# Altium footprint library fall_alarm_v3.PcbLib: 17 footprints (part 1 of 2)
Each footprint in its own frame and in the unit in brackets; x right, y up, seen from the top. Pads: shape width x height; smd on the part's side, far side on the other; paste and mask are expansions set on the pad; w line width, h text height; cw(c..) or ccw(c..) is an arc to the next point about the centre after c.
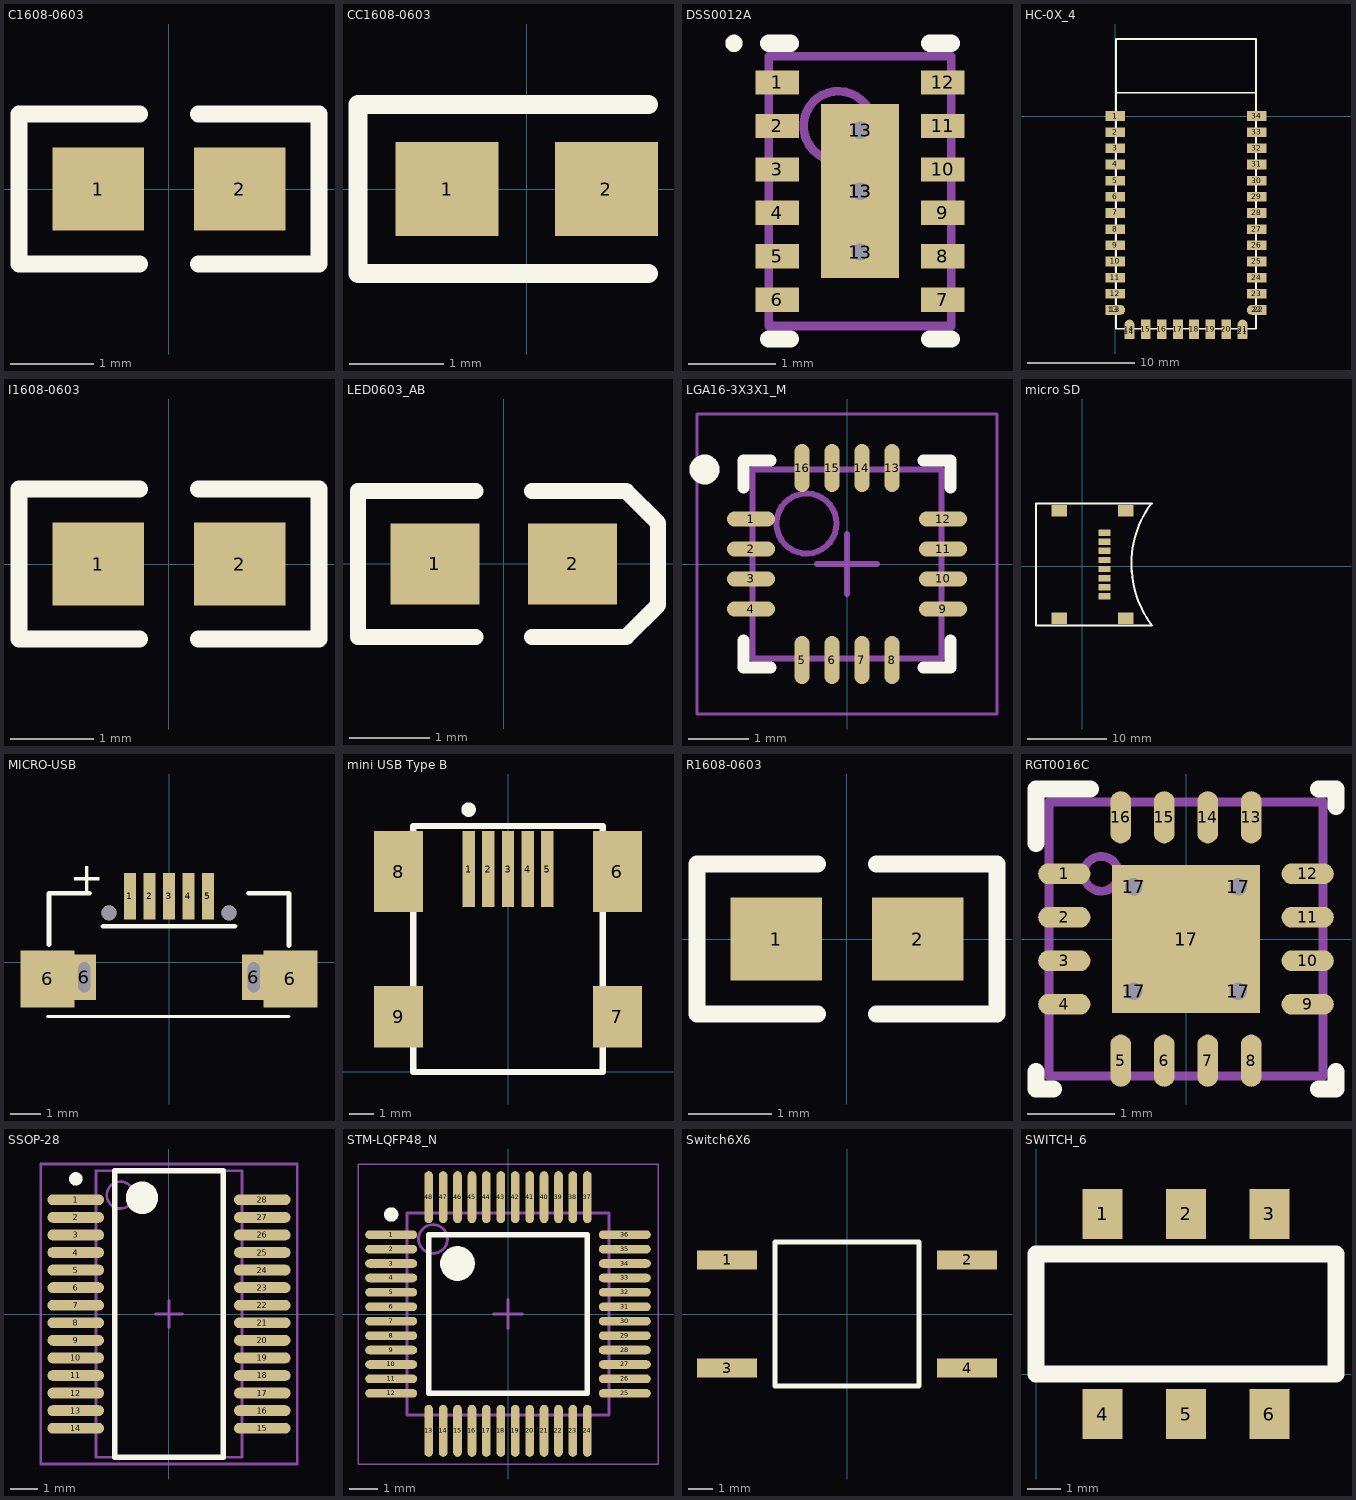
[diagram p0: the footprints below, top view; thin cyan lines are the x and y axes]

## C1608-0603 [mm]
pads (2):
  rect 1.1x1 smd: 1(-0.85,0) 2(0.85,0)
Top Overlay:
  lines w0.2: -0.35,-0.9 -1.8,-0.9 -1.8,0.9 -0.35,0.9 ; 0.35,-0.9 1.8,-0.9 1.8,0.9 0.35,0.9

## CC1608-0603 [mm]
pads (2):
  rect 1.1x1 smd: 1(-0.85,0) 2(0.85,0)
Top Overlay:
  lines w0.2: 1.3,-0.9 -1.8,-0.9 -1.8,0.9 1.3,0.9

## DSS0012A [mm]
pads (16):
  rect 0.5x0.28 smd paste-0.14 mask+0.076: 1(47.31,52.05) 2(47.31,51.55) 3(47.31,51.05) 4(47.31,50.55) 5(47.31,50.05) 6(47.31,49.55) 7(49.21,49.55) 8(49.21,50.05) 9(49.21,50.55) 10(49.21,51.05) 11(49.21,51.55) 12(49.21,52.05)
  round 0.5 / inner round 1.524 / far side round 0.5 hole 0.2 mask+0.051: 13(48.26,50.8) 13(48.26,50.1) 13(48.26,51.5)
  rect 0.9x2 smd paste-0.45 mask+0.076: 13(48.26,50.8)
Top Overlay:
  circle w0.1: c46.81,52.5 r0.05
  lines w0.2: 47.21,49.1 47.46,49.1 ; 47.21,52.5 47.46,52.5 ; 49.06,49.1 49.31,49.1 ; 49.06,52.5 49.31,52.5
Top Paste:
  region: 47.06,51.175 47.06,50.925 47.56,50.925 47.56,51.175
  region: 47.885,52.5 47.885,51.9 48.135,51.9 48.135,52.5
  region: 47.91,51.6 47.91,50 48.61,50 48.61,51.6
  region: 48.635,51.9 48.635,52.5 48.385,52.5 48.385,51.9
  region: 48.635,49.1 48.635,49.7 48.385,49.7 48.385,49.1
  region: 47.885,49.7 47.885,49.1 48.135,49.1 48.135,49.7
  region: 47.06,51.675 47.06,51.425 47.56,51.425 47.56,51.675
  region: 47.06,52.175 47.06,51.925 47.56,51.925 47.56,52.175
  region: 47.06,50.675 47.06,50.425 47.56,50.425 47.56,50.675
  region: 47.06,50.175 47.06,49.925 47.56,49.925 47.56,50.175
  region: 47.06,49.675 47.06,49.425 47.56,49.425 47.56,49.675
  region: 48.96,49.675 48.96,49.425 49.46,49.425 49.46,49.675
  region: 48.96,50.175 48.96,49.925 49.46,49.925 49.46,50.175
  region: 48.96,50.675 48.96,50.425 49.46,50.425 49.46,50.675
  region: 48.96,51.175 48.96,50.925 49.46,50.925 49.46,51.175
  region: 48.96,51.675 48.96,51.425 49.46,51.425 49.46,51.675
  region: 48.96,52.175 48.96,51.925 49.46,51.925 49.46,52.175
Mechanical 1:
  circle w0.1: c48.01,51.55 r0.4
  lines w0.1: 47.21,49.25 47.21,52.35 49.31,52.35 49.31,49.25 47.21,49.25

## HC-0X_4 [mm]
pads (38):
  rect 1.8x0.9 smd: 1(0,0) 2(0,-1.5) 3(0,-3) 4(0,-4.5) 5(0,-6) 6(0,-7.5) 7(0,-9) 8(0,-10.5) 9(0,-12) 10(0,-13.5) 11(0,-15) 12(0,-16.5) 23(13.1,-16.5) 24(13.1,-15) 25(13.1,-13.5) 26(13.1,-12) 27(13.1,-10.5) 28(13.1,-9) 29(13.1,-7.5) 30(13.1,-6) 31(13.1,-4.5) 32(13.1,-3) 33(13.1,-1.5) 34(13.1,0)
  rect 1.35x0.9 smd: 13(-0.225,-18) 22(13.325,-18)
  oval 1.8x0.9 smd: 13(0,-18) 22(13.1,-18)
  rect 0.9x1.35 smd: 14(1.3,-20.025) 21(11.8,-20.025)
  oval 0.9x1.8 smd: 14(1.3,-19.8) 21(11.8,-19.8)
  rect 0.9x1.8 smd: 15(2.8,-19.8) 16(4.3,-19.8) 17(5.8,-19.8) 18(7.3,-19.8) 19(8.8,-19.8) 20(10.3,-19.8)
Top Overlay:
  lines w0.152: 0.05,2.15 13.05,2.15 ; 0.05,-19.75 0.05,7.15 13.05,7.15 13.05,-19.75 0.05,-19.75

## I1608-0603 [mm]
pads (2):
  rect 1.1x1 smd: 1(-0.85,0) 2(0.85,0)
Top Overlay:
  lines w0.2: -0.35,-0.9 -1.8,-0.9 -1.8,0.9 -0.35,0.9 ; 0.35,-0.9 1.8,-0.9 1.8,0.9 0.35,0.9

## LED0603_AB [mm]
pads (2):
  rect 1.1x1 smd: 1(-0.85,0) 2(0.85,0)
Top Overlay:
  lines w0.2: -0.35,-0.9 -1.8,-0.9 -1.8,0.9 -0.35,0.9 ; 0.35,-0.9 1.513,-0.9 1.905,-0.508 1.905,0.508 1.513,0.9 0.35,0.9

## LGA16-3X3X1_M [mm] "PQFN, 16-Leads, Body 3x3mm, Pitch 0.5mm, IPC Low Density"
height 1
pads (16):
  oval 0.8x0.25 smd: 1(-1.6,0.75) 2(-1.6,0.25) 3(-1.6,-0.25) 4(-1.6,-0.75) 9(1.6,-0.75) 10(1.6,-0.25) 11(1.6,0.25) 12(1.6,0.75)
  oval 0.25x0.8 smd: 5(-0.75,-1.6) 6(-0.25,-1.6) 7(0.25,-1.6) 8(0.75,-1.6) 13(0.75,1.6) 14(0.25,1.6) 15(-0.25,1.6) 16(-0.75,1.6)
Top Overlay:
  circle w0.25: c-2.375,1.575 r0.125
  lines w0.2: -1.725,-1.275 -1.725,-1.725 -1.275,-1.725 ; -1.725,1.275 -1.725,1.725 -1.275,1.725 ; 1.275,-1.725 1.725,-1.725 1.725,-1.275 ; 1.275,1.725 1.725,1.725 1.725,1.275
Mechanical 13:
  circle w0.1: c-0.675,0.675 r0.5
  lines w0.1: -1.575,-1.575 1.575,-1.575 1.575,1.575 -1.575,1.575 -1.575,-1.575
Mechanical 15:
  lines w0.05: -2.5,-2.5 2.5,-2.5 2.5,2.5 -2.5,2.5 -2.5,-2.5
  lines w0.1: -0.5,0 0.5,0 ; 0,-0.5 0,0.5
3D body: height 1, standoff 0, extent -1.575,-1.575 1.575,1.575

## micro SD [mm]
pads (12):
  rect 1.5x0.8 smd: 1(2.794,4.191) 2(2.794,3.048) 3(2.794,1.905) 4(2.794,0.762) 5(2.794,-0.381) 6(2.794,-1.524) 7(2.794,-2.667) 8(2.794,-3.81)
  rect 2x1.45 smd: ""(-2.921,-6.604) ""(-2.921,6.985) ""(5.461,-6.604) ""(5.461,6.985)
Top Overlay:
  lines w0.254: 8.614,7.798 ccw(c19.05,0.254) 8.763,-7.493 -5.842,-7.493 -5.842,7.874 8.763,7.874

## MICRO-USB [mm]
pads (11):
  rect 0.4x1.55 smd: 1(-1.3,2.2) 2(-0.65,2.2) 3(0,2.2) 4(0.65,2.2) 5(1.3,2.2)
  rect 1.8x1.9 smd: 6(-4.05,-0.55) 6(4.05,-0.55)
  rect 0.8x1.5 hole 0.4 slot 1 at 90 deg: 6(-2.825,-0.5) 6(2.825,-0.5)
  round 0.5 hole 0.5 unplated: ""(-2,1.65) ""(2,1.65)
Top Overlay:
  lines w0.1: -4.05,-1.8 4,-1.8
  lines w0.152: -4,0.584 -4,2.3 -2.65,2.3 ; -2.2,1.2 2.2,1.2 ; 2.65,2.3 4,2.3 4,0.55
  text "+" at -3.3,2.35 h1

## mini USB Type B [mm]
pads (9):
  rect 0.5x3.1 smd: 1(-1.6,8.25) 2(-0.8,8.25) 3(0,8.25) 4(0.8,8.25) 5(1.6,8.25)
  rect 2x3.3 smd: 6(4.45,8.15) 8(-4.45,8.15)
  rect 2x2.5 smd: 7(4.45,2.25) 9(-4.45,2.25)
Top Overlay:
  circle w0.3: c-1.6,10.668 r0.146
  lines w0.254: -3.85,0 3.85,0 3.85,10 -3.85,10 -3.85,0

## R1608-0603 [mm]
pads (2):
  rect 1.1x1 smd: 1(-0.85,0) 2(0.85,0)
Top Overlay:
  lines w0.2: -0.35,-0.9 -1.8,-0.9 -1.8,0.9 -0.35,0.9 ; 0.35,-0.9 1.8,-0.9 1.8,0.9 0.35,0.9

## RGT0016C [mm]
pads (21):
  oval 0.6x0.24 smd paste-0.102 mask+0.051: 1(-1.4,0.75) 2(-1.4,0.25) 3(-1.4,-0.25) 4(-1.4,-0.75) 9(1.4,-0.75) 10(1.4,-0.25) 11(1.4,0.25) 12(1.4,0.75)
  oval 0.24x0.6 smd paste-0.102 mask+0.051: 5(-0.75,-1.4) 6(-0.25,-1.4) 7(0.25,-1.4) 8(0.75,-1.4) 13(0.75,1.4) 14(0.25,1.4) 15(-0.25,1.4) 16(-0.75,1.4)
  round 0.5 / inner round 1.524 / far side round 0.5 hole 0.203 mask+0.051: 17(-0.6,-0.6) 17(-0.6,0.6) 17(0.6,-0.6) 17(0.6,0.6)
  rect 1.7x1.7 smd paste-0.837 mask+0.051: 17(0,0)
Top Overlay:
  lines w0.2: -1.725,-1.525 -1.725,-1.725 -1.525,-1.725 ; -1.725,1.1 -1.725,1.725 -1.1,1.725 ; 1.525,-1.725 1.725,-1.725 1.725,-1.525 ; 1.525,1.725 1.725,1.725 1.725,1.525
Top Paste:
  region: -0.774,0.774 -0.774,-0.774 0.774,-0.774 0.774,0.774
Mechanical 1:
  circle w0.1: c-0.975,0.75 r0.2
  lines w0.1: -1.575,-1.575 1.575,-1.575 1.575,1.575 -1.575,1.575 -1.575,-1.575

## SSOP-28 [mm] "28-Pin SSOP 0.65 mm Pitch"
height 2
pads (28):
  oval 2.1x0.4 smd: 1(-3.45,4.225) 2(-3.45,3.575) 3(-3.45,2.925) 4(-3.45,2.275) 5(-3.45,1.625) 6(-3.45,0.975) 7(-3.45,0.325) 8(-3.45,-0.325) 9(-3.45,-0.975) 10(-3.45,-1.625) 11(-3.45,-2.275) 12(-3.45,-2.925) 13(-3.45,-3.575) 14(-3.45,-4.225) 15(3.45,-4.225) 16(3.45,-3.575) 17(3.45,-2.925) 18(3.45,-2.275) 19(3.45,-1.625) 20(3.45,-0.975) 21(3.45,-0.325) 22(3.45,0.325) 23(3.45,0.975) 24(3.45,1.625) 25(3.45,2.275) 26(3.45,2.925) 27(3.45,3.575) 28(3.45,4.225)
Top Overlay:
  circle w0.25: c-3.45,5 r0.125
  circle w0.6: c-1,4.3 r0.3
  lines w0.2: -2,-5.3 -2,5.3 2,5.3 2,-5.3 -2,-5.3
Mechanical 13:
  circle w0.1: c-1.8,4.4 r0.5
  lines w0.1: -2.7,-5.3 -2.7,5.3 2.7,5.3 2.7,-5.3 -2.7,-5.3
Mechanical 15:
  lines w0.1: -0.5,0 0.5,0 ; 0,-0.5 0,0.5 ; -4.75,-5.55 -4.75,5.55 4.75,5.55 4.75,-5.55 -4.75,-5.55
3D body: height 2, standoff 0, extent -2.7,-5.3 2.7,5.3

## STM-LQFP48_N [mm] "QFP, 48-Leads, Body 7x7mm, Pitch 0.5mm, IPC Medium Density"
height 1.6
pads (48):
  oval 1.8x0.3 smd: 1(-4.05,2.75) 2(-4.05,2.25) 3(-4.05,1.75) 4(-4.05,1.25) 5(-4.05,0.75) 6(-4.05,0.25) 7(-4.05,-0.25) 8(-4.05,-0.75) 9(-4.05,-1.25) 10(-4.05,-1.75) 11(-4.05,-2.25) 12(-4.05,-2.75) 25(4.05,-2.75) 26(4.05,-2.25) 27(4.05,-1.75) 28(4.05,-1.25) 29(4.05,-0.75) 30(4.05,-0.25) 31(4.05,0.25) 32(4.05,0.75) 33(4.05,1.25) 34(4.05,1.75) 35(4.05,2.25) 36(4.05,2.75)
  oval 0.3x1.8 smd: 13(-2.75,-4.05) 14(-2.25,-4.05) 15(-1.75,-4.05) 16(-1.25,-4.05) 17(-0.75,-4.05) 18(-0.25,-4.05) 19(0.25,-4.05) 20(0.75,-4.05) 21(1.25,-4.05) 22(1.75,-4.05) 23(2.25,-4.05) 24(2.75,-4.05) 37(2.75,4.05) 38(2.25,4.05) 39(1.75,4.05) 40(1.25,4.05) 41(0.75,4.05) 42(0.25,4.05) 43(-0.25,4.05) 44(-0.75,4.05) 45(-1.25,4.05) 46(-1.75,4.05) 47(-2.25,4.05) 48(-2.75,4.05)
Top Overlay:
  circle w0.25: c-4.05,3.45 r0.125
  circle w0.6: c-1.75,1.75 r0.3
  lines w0.2: -2.75,-2.75 -2.75,2.75 2.75,2.75 2.75,-2.75 -2.75,-2.75
Mechanical 13:
  circle w0.1: c-2.6,2.6 r0.5
  lines w0.1: -3.5,-3.5 -3.5,3.5 3.5,3.5 3.5,-3.5 -3.5,-3.5
Mechanical 15:
  lines w0.05: -5.2,-5.2 -5.2,5.2 5.2,5.2 5.2,-5.2 -5.2,-5.2
  lines w0.1: -0.5,0 0.5,0 ; 0,-0.5 0,0.5
3D body: height 1.6, standoff 0.05, extent -3.5,-3.5 3.5,3.5

## Switch6X6 [mm]
pads (4):
  rect 2.5x0.8 smd: 1(-5,2.25) 2(5,2.25) 3(-5,-2.25) 4(5,-2.25)
Top Overlay:
  lines w0.2: -3,-3 -3,3 3,3 3,-3 -3,-3

## SWITCH_6 [mm]
pads (6):
  rect 1.2x1.5 smd: 1(2,4.8) 2(4.5,4.8) 3(7,4.8) 4(2,-1.2) 5(4.5,-1.2) 6(7,-1.2)
Top Overlay:
  lines w0.508: 0,0 9,0 9,3.6 0,3.6 0,0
